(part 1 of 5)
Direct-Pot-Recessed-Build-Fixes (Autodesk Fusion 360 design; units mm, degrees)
parameter "FrameLength" = 640 comment "Fixed existing outer length"
parameter "FrameWidth" = 190 comment "Fixed existing outer width"
parameter "FrameHeight" = 110 comment "Fixed existing height"
parameter "PivotHeight" = 30 comment "Above frame center"
parameter "LeverTravel" = 100 comment "Stable endpoint to endpoint"
parameter "PrintClearance" = 0.3 comment "Prototype diametral running clearance"
base_mesh_feature "Base Mesh Feature"
ground "Pin1"
work_plane "WorkPlane1" AlongDistance -36 ExtraOffset 0
sketch "Flat load-bearing plate" plane through (-36, 0, 0) normal (1, 0, 0) x axis (0, 0, -1)
  line L1 (-33, -55) -> (-33, -75)
  line L2 (2, -55) -> (-33, -55)
  line L3 (2, 55) -> (2, -55)
  line L4 (-33, 55) -> (2, 55)
  line L5 (-33, 75) -> (-33, 55)
  line L6 (-57, 75) -> (-33, 75)
  line L7 (-57, 32) -> (-57, 75)
  line L8 (-86, 26) -> (-57, 32)
  line L9 (-86, -26) -> (-86, 26)
  line L10 (-57, -32) -> (-86, -26)
  line L11 (-57, -75) -> (-57, -32)
  line L12 (-33, -75) -> (-57, -75)
extrude "Extrude1" new body sketch "Flat load-bearing plate" along normal blind 12
work_plane "WorkPlane2" AlongDistance -37 ExtraOffset 0
sketch "Replaceable bushing seat" plane through (-37, 0, 0) normal (1, 0, 0) x axis (0, 0, -1)
  circle C1 centre (-65, 0) radius 10.15
extrude "Extrude2" cut sketch "Replaceable bushing seat" along normal blind 14
work_plane "WorkPlane3" AlongDistance -37 ExtraOffset 0
sketch "Follower pivot bolt" plane through (-37, 0, 0) normal (1, 0, 0) x axis (0, 0, -1)
  circle C1 centre (-12, -35) radius 2.7
extrude "Extrude3" cut sketch "Follower pivot bolt" along normal blind 14
work_plane "WorkPlane4" AlongDistance -76 ExtraOffset 0
sketch "M5 rail mounting bore" plane through (0, -76, 0) normal (0, 1, 0) x axis (1, 0, 0)
  circle C1 centre (-30, -45) radius 2.7
extrude "Extrude4" cut sketch "M5 rail mounting bore" along normal blind 22
work_plane "WorkPlane5" AlongDistance -55 ExtraOffset 0
sketch "Rail screw tool and washer access" plane through (0, -55, 0) normal (0, 1, 0) x axis (1, 0, 0)
  circle C1 centre (-30, -45) radius 5.3
extrude "Extrude5" cut sketch "Rail screw tool and washer access" along normal blind 12
work_plane "WorkPlane6" AlongDistance 54 ExtraOffset 0
sketch "M5 rail mounting bore (1)" plane through (0, 54, 0) normal (0, 1, 0) x axis (1, 0, 0)
  circle C1 centre (-30, -45) radius 2.7
extrude "Extrude6" cut sketch "M5 rail mounting bore (1)" along normal blind 22
work_plane "WorkPlane7" AlongDistance 43 ExtraOffset 0
sketch "Rail screw tool and washer access (1)" plane through (0, 43, 0) normal (0, 1, 0) x axis (1, 0, 0)
  circle C1 centre (-30, -45) radius 5.3
extrude "Extrude7" cut sketch "Rail screw tool and washer access (1)" along normal blind 12
work_plane "WorkPlane8" AlongDistance -37 ExtraOffset 0
sketch "Spring crossblock attachment" plane through (-37, 0, 0) normal (1, 0, 0) x axis (0, 0, -1)
  circle C1 centre (-44, -59) radius 1.7
extrude "Extrude8" cut sketch "Spring crossblock attachment" along normal blind 14
work_plane "WorkPlane9" AlongDistance -37 ExtraOffset 0
sketch "Spring crossblock attachment (1)" plane through (-37, 0, 0) normal (1, 0, 0) x axis (0, 0, -1)
  circle C1 centre (-44, -51) radius 1.7
extrude "Extrude9" cut sketch "Spring crossblock attachment (1)" along normal blind 14
work_plane "WorkPlane1" AlongDistance 24 ExtraOffset 0
sketch "Flat load-bearing plate" plane through (24, 0, 0) normal (1, 0, 0) x axis (0, 0, -1)
  line L1 (-33, -55) -> (-33, -75)
  line L2 (2, -55) -> (-33, -55)
  line L3 (2, 55) -> (2, -55)
  line L4 (-33, 55) -> (2, 55)
  line L5 (-33, 75) -> (-33, 55)
  line L6 (-57, 75) -> (-33, 75)
  line L7 (-57, 32) -> (-57, 75)
  line L8 (-86, 26) -> (-57, 32)
  line L9 (-86, -26) -> (-86, 26)
  line L10 (-57, -32) -> (-86, -26)
  line L11 (-57, -75) -> (-57, -32)
  line L12 (-33, -75) -> (-57, -75)
extrude "Extrude1" new body sketch "Flat load-bearing plate" along normal blind 12
work_plane "WorkPlane2" AlongDistance 23 ExtraOffset 0
sketch "Replaceable bushing seat" plane through (23, 0, 0) normal (1, 0, 0) x axis (0, 0, -1)
  circle C1 centre (-65, 0) radius 10.15
extrude "Extrude2" cut sketch "Replaceable bushing seat" along normal blind 14
work_plane "WorkPlane3" AlongDistance 23 ExtraOffset 0
sketch "Follower pivot bolt" plane through (23, 0, 0) normal (1, 0, 0) x axis (0, 0, -1)
  circle C1 centre (-12, -35) radius 2.7
extrude "Extrude3" cut sketch "Follower pivot bolt" along normal blind 14
work_plane "WorkPlane4" AlongDistance -76 ExtraOffset 0
sketch "M5 rail mounting bore" plane through (0, -76, 0) normal (0, 1, 0) x axis (1, 0, 0)
  circle C1 centre (30, -45) radius 2.7
extrude "Extrude4" cut sketch "M5 rail mounting bore" along normal blind 22
work_plane "WorkPlane5" AlongDistance -55 ExtraOffset 0
sketch "Rail screw tool and washer access" plane through (0, -55, 0) normal (0, 1, 0) x axis (1, 0, 0)
  circle C1 centre (30, -45) radius 5.3
extrude "Extrude5" cut sketch "Rail screw tool and washer access" along normal blind 12
work_plane "WorkPlane6" AlongDistance 54 ExtraOffset 0
sketch "M5 rail mounting bore (1)" plane through (0, 54, 0) normal (0, 1, 0) x axis (1, 0, 0)
  circle C1 centre (30, -45) radius 2.7
extrude "Extrude6" cut sketch "M5 rail mounting bore (1)" along normal blind 22
work_plane "WorkPlane7" AlongDistance 43 ExtraOffset 0
sketch "Rail screw tool and washer access (1)" plane through (0, 43, 0) normal (0, 1, 0) x axis (1, 0, 0)
  circle C1 centre (30, -45) radius 5.3
extrude "Extrude7" cut sketch "Rail screw tool and washer access (1)" along normal blind 12
work_plane "WorkPlane8" AlongDistance 23 ExtraOffset 0
sketch "Spring crossblock attachment" plane through (23, 0, 0) normal (1, 0, 0) x axis (0, 0, -1)
  circle C1 centre (-44, -59) radius 1.7
extrude "Extrude8" cut sketch "Spring crossblock attachment" along normal blind 14
work_plane "WorkPlane9" AlongDistance 23 ExtraOffset 0
sketch "Spring crossblock attachment (1)" plane through (23, 0, 0) normal (1, 0, 0) x axis (0, 0, -1)
  circle C1 centre (-44, -51) radius 1.7
extrude "Extrude9" cut sketch "Spring crossblock attachment (1)" along normal blind 14
work_plane "WorkPlane1" AlongDistance -36 ExtraOffset 0
sketch "Replaceable journal body" plane through (-36, 0, 0) normal (1, 0, 0) x axis (0, 0, -1)
  circle C1 centre (-65, 0) radius 10.05
extrude "Extrude1" new body sketch "Replaceable journal body" along normal blind 12 bodies "P03 Left flanged journal bush"
work_plane "WorkPlane2" AlongDistance -37.2 ExtraOffset 0
sketch "Axial thrust flange" plane through (-37.2, 0, 0) normal (1, 0, 0) x axis (0, 0, -1)
  circle C1 centre (-65, 0) radius 12.75
extrude "Extrude2" add sketch "Axial thrust flange" along normal blind 1.2
work_plane "WorkPlane3" AlongDistance -38 ExtraOffset 0
sketch "Running journal bore" plane through (-38, 0, 0) normal (1, 0, 0) x axis (0, 0, -1)
  circle C1 centre (-65, 0) radius 6.15
extrude "Extrude3" cut sketch "Running journal bore" along normal blind 15
work_plane "WorkPlane1" AlongDistance 24 ExtraOffset 0
sketch "Replaceable journal body" plane through (24, 0, 0) normal (1, 0, 0) x axis (0, 0, -1)
  circle C1 centre (-65, 0) radius 10.05
extrude "Extrude1" new body sketch "Replaceable journal body" along normal blind 12 bodies "P04 Right bush lower half"
work_plane "WorkPlane2" AlongDistance 36 ExtraOffset 0
sketch "Axial thrust flange" plane through (36, 0, 0) normal (1, 0, 0) x axis (0, 0, -1)
  circle C1 centre (-65, 0) radius 12.75
extrude "Extrude2" add sketch "Axial thrust flange" along normal blind 1.2
work_plane "WorkPlane3" AlongDistance 23 ExtraOffset 0
sketch "Running journal bore" plane through (23, 0, 0) normal (1, 0, 0) x axis (0, 0, -1)
  circle C1 centre (-65, 0) radius 6.15
extrude "Extrude3" cut sketch "Running journal bore" along normal blind 15
work_plane "WorkPlane1" AlongDistance -37.35 ExtraOffset 0
sketch "Continuous 12 mm journals" plane through (-37.35, 0, 0) normal (1, 0, 0) x axis (0, 0, -1)
  circle C1 centre (-65, 0) radius 6
extrude "Extrude1" new body sketch "Continuous 12 mm journals" along normal blind 74.7 bodies "P05 Shaft lower half"
work_plane "WorkPlane2" AlongDistance -23.8 ExtraOffset 0
sketch "16 mm structural shaft" plane through (-23.8, 0, 0) normal (1, 0, 0) x axis (0, 0, -1)
  circle C1 centre (-65, 0) radius 8
extrude "Extrude2" add sketch "16 mm structural shaft" along normal blind 47.6
work_plane "WorkPlane3" AlongDistance -23.9 ExtraOffset 0
sketch "D-flat torque key" plane through (-23.9, 0, 0) normal (1, 0, 0) x axis (0, 0, -1)
  line L1 (-56, 9) -> (-56, 6.5)
  line L2 (-74, 9) -> (-56, 9)
  line L3 (-74, 6.5) -> (-74, 9)
  line L4 (-56, 6.5) -> (-74, 6.5)
extrude "Extrude3" cut sketch "D-flat torque key" along normal blind 47.8
work_plane "WorkPlane4" AlongDistance 37.35 ExtraOffset 0
sketch "Integral axial shoulder" plane through (37.35, 0, 0) normal (1, 0, 0) x axis (0, 0, -1)
  circle C1 centre (-65, 0) radius 10
extrude "Extrude4" add sketch "Integral axial shoulder" along normal blind 3
work_plane "WorkPlane5" AlongDistance 40.35 ExtraOffset 0
sketch "Sensor drive stub" plane through (40.35, 0, 0) normal (1, 0, 0) x axis (0, 0, -1)
  circle C1 centre (-65, 0) radius 4
extrude "Extrude5" add sketch "Sensor drive stub" along normal blind 10
work_plane "WorkPlane6" AlongDistance 40.25 ExtraOffset 0
sketch "Sensor drive flat" plane through (40.25, 0, 0) normal (1, 0, 0) x axis (0, 0, -1)
  line L1 (-60, 5) -> (-60, 3.2)
  line L2 (-70, 5) -> (-60, 5)
  line L3 (-70, 3.2) -> (-70, 5)
  line L4 (-60, 3.2) -> (-70, 3.2)
extrude "Extrude6" cut sketch "Sensor drive flat" along normal blind 10.25
work_plane "WorkPlane7" AlongDistance -37.45 ExtraOffset 0
sketch "M3 heat-set end retention" plane through (-37.45, 0, 0) normal (1, 0, 0) x axis (0, 0, -1)
  circle C1 centre (-65, 0) radius 1.7
extrude "Extrude7" cut sketch "M3 heat-set end retention" along normal blind 6.8
work_plane "WorkPlane1" AlongDistance -39.35 ExtraOffset 0
sketch "Axial cap" plane through (-39.35, 0, 0) normal (1, 0, 0) x axis (0, 0, -1)
  circle C1 centre (-65, 0) radius 10
extrude "Extrude1" new body sketch "Axial cap" along normal blind 2 bodies "P06 Shaft retaining cap"
work_plane "WorkPlane2" AlongDistance -39.5 ExtraOffset 0
sketch "M3 cap screw" plane through (-39.5, 0, 0) normal (1, 0, 0) x axis (0, 0, -1)
  circle C1 centre (-65, 0) radius 1.7
extrude "Extrude2" cut sketch "M3 cap screw" along normal blind 2.4
work_plane "WorkPlane1" AlongDistance -7 ExtraOffset 0
sketch "Main lever hub" plane through (-7, 0, 0) normal (1, 0, 0) x axis (0, 0, -1)
  circle C1 centre (-65, 0) radius 22
extrude "Extrude1" new body sketch "Main lever hub" along normal blind 14 bodies "P07 Integral lever rotor and cam carrier"
work_plane "WorkPlane2" AlongDistance -7 ExtraOffset 0
sketch "Continuous reinforced lever stem" plane through (-7, 0, 0) normal (1, 0, 0) x axis (0, 0, -1)
  line L1 (-60, 14) -> (-60, -14)
  line L2 (-95, 11) -> (-60, 14)
  line L3 (-150, 7) -> (-95, 11)
  line L4 (-195, 7) -> (-150, 7)
  line L5 (-195, -7) -> (-195, 7)
  line L6 (-150, -7) -> (-195, -7)
  line L7 (-95, -11) -> (-150, -7)
  line L8 (-60, -14) -> (-95, -11)
extrude "Extrude2" add sketch "Continuous reinforced lever stem" along normal blind 14
work_plane "WorkPlane3" AlongDistance -7 ExtraOffset 0
sketch "Integrated cam carrier fan" plane through (-7, 0, 0) normal (1, 0, 0) x axis (0, 0, -1)
  line L1 (-44.5, 35.507) -> (-65, 0)
  line L2 (-42.6698, 34.3855) -> (-44.5, 35.507)
  line L3 (-40.9008, 33.1697) -> (-42.6698, 34.3855)
  line L4 (-39.1979, 31.863) -> (-40.9008, 33.1697)
  line L5 (-37.5656, 30.4689) -> (-39.1979, 31.863)
  line L6 (-36.0086, 28.9914) -> (-37.5656, 30.4689)
  line L7 (-34.5311, 27.4344) -> (-36.0086, 28.9914)
  line L8 (-33.137, 25.8021) -> (-34.5311, 27.4344)
  line L9 (-31.8303, 24.0992) -> (-33.137, 25.8021)
  line L10 (-30.6145, 22.3302) -> (-31.8303, 24.0992)
  line L11 (-29.493, 20.5) -> (-30.6145, 22.3302)
  line L12 (-28.4687, 18.6136) -> (-29.493, 20.5)
  line L13 (-27.5446, 16.6762) -> (-28.4687, 18.6136)
  line L14 (-26.7232, 14.6931) -> (-27.5446, 16.6762)
  line L15 (-26.0067, 12.6697) -> (-26.7232, 14.6931)
  line L16 (-25.397, 10.6116) -> (-26.0067, 12.6697)
  line L17 (-24.8959, 8.5244) -> (-25.397, 10.6116)
  line L18 (-24.5048, 6.4138) -> (-24.8959, 8.5244)
  line L19 (-24.2246, 4.2857) -> (-24.5048, 6.4138)
  line L20 (-24.0562, 2.1458) -> (-24.2246, 4.2857)
  line L21 (-24, 0) -> (-24.0562, 2.1458)
  line L22 (-24.0562, -2.1458) -> (-24, 0)
  line L23 (-24.2246, -4.2857) -> (-24.0562, -2.1458)
  line L24 (-24.5048, -6.4138) -> (-24.2246, -4.2857)
  line L25 (-24.8959, -8.5244) -> (-24.5048, -6.4138)
  line L26 (-25.397, -10.6116) -> (-24.8959, -8.5244)
  line L27 (-26.0067, -12.6697) -> (-25.397, -10.6116)
  line L28 (-26.7232, -14.6931) -> (-26.0067, -12.6697)
  line L29 (-27.5446, -16.6762) -> (-26.7232, -14.6931)
  line L30 (-28.4687, -18.6136) -> (-27.5446, -16.6762)
  line L31 (-29.493, -20.5) -> (-28.4687, -18.6136)
  line L32 (-30.6145, -22.3302) -> (-29.493, -20.5)
  line L33 (-31.8303, -24.0992) -> (-30.6145, -22.3302)
  line L34 (-33.137, -25.8021) -> (-31.8303, -24.0992)
  line L35 (-34.5311, -27.4344) -> (-33.137, -25.8021)
  line L36 (-36.0086, -28.9914) -> (-34.5311, -27.4344)
  line L37 (-37.5656, -30.4689) -> (-36.0086, -28.9914)
  line L38 (-39.1979, -31.863) -> (-37.5656, -30.4689)
  line L39 (-40.9008, -33.1697) -> (-39.1979, -31.863)
  line L40 (-42.6698, -34.3855) -> (-40.9008, -33.1697)
  line L41 (-44.5, -35.507) -> (-42.6698, -34.3855)
  line L42 (-65, 0) -> (-44.5, -35.507)
extrude "Extrude3" add sketch "Integrated cam carrier fan" along normal blind 14
work_plane "WorkPlane4" AlongDistance -23.6 ExtraOffset 0
sketch "Integral axial locating hub" plane through (-23.6, 0, 0) normal (1, 0, 0) x axis (0, 0, -1)
  circle C1 centre (-65, 0) radius 10
work_plane "WorkPlane5" AlongDistance -24 ExtraOffset 0
sketch "D shaft socket" plane through (-24, 0, 0) normal (1, 0, 0) x axis (0, 0, -1)
  line L1 (-69.6247, 6.65) -> (-60.3753, 6.65)
  arc A1 centre (-65, 0) radius 8.1 clockwise from (-60.3753, 6.65) to (-69.6247, 6.65)
extrude "Extrude5" cut sketch "D shaft socket" along normal blind 48
work_plane "WorkPlane6" AlongDistance 0.3 ExtraOffset 0
sketch "Cam M3 insert pocket" plane through (0.3, 0, 0) normal (1, 0, 0) x axis (0, 0, -1)
  circle C1 centre (-39.5442, 25.4558) radius 1.7
extrude "Extrude6" cut sketch "Cam M3 insert pocket" along normal blind 6.8
work_plane "WorkPlane7" AlongDistance 0.3 ExtraOffset 0
sketch "Cam M3 insert pocket (1)" plane through (0.3, 0, 0) normal (1, 0, 0) x axis (0, 0, -1)
  circle C1 centre (-29, 0) radius 1.7
extrude "Extrude7" cut sketch "Cam M3 insert pocket (1)" along normal blind 6.8
work_plane "WorkPlane8" AlongDistance 0.3 ExtraOffset 0
sketch "Cam M3 insert pocket (2)" plane through (0.3, 0, 0) normal (1, 0, 0) x axis (0, 0, -1)
  circle C1 centre (-39.5442, -25.4558) radius 1.7
extrude "Extrude8" cut sketch "Cam M3 insert pocket (2)" along normal blind 6.8
work_plane "WorkPlane9" AlongDistance -8 ExtraOffset 0
sketch "Grip through bolt" plane through (-8, 0, 0) normal (1, 0, 0) x axis (0, 0, -1)
  circle C1 centre (-180, 0) radius 1.7
extrude "Extrude9" cut sketch "Grip through bolt" along normal blind 16
work_plane "WorkPlane10" AlongDistance -8 ExtraOffset 0
sketch "Grip through bolt (1)" plane through (-8, 0, 0) normal (1, 0, 0) x axis (0, 0, -1)
  circle C1 centre (-190, 0) radius 1.7
extrude "Extrude10" cut sketch "Grip through bolt (1)" along normal blind 16
work_plane "WorkPlane1" AlongDistance 7 ExtraOffset 0
sketch "Roller compensated replaceable cam" plane through (7, 0, 0) normal (1, 0, 0) x axis (0, 0, -1)
  line L1 (-39.4967, 42.2602) -> (-39.6212, 42.3096)
  line L2 (-39.3834, 42.211) -> (-39.4967, 42.2602)
  line L3 (-39.2796, 42.1617) -> (-39.3834, 42.211)
  line L4 (-39.1836, 42.1119) -> (-39.2796, 42.1617)
  line L5 (-39.0932, 42.0608) -> (-39.1836, 42.1119)
  line L6 (-39.0065, 42.0075) -> (-39.0932, 42.0608)
  line L7 (-38.9215, 41.9508) -> (-39.0065, 42.0075)
  line L8 (-38.8363, 41.8895) -> (-38.9215, 41.9508)
  line L9 (-38.7492, 41.8219) -> (-38.8363, 41.8895)
  line L10 (-38.6586, 41.7465) -> (-38.7492, 41.8219)
  line L11 (-38.5633, 41.6619) -> (-38.6586, 41.7465)
  line L12 (-38.4623, 41.5665) -> (-38.5633, 41.6619)
  line L13 (-38.3549, 41.459) -> (-38.4623, 41.5665)
  line L14 (-38.2404, 41.3384) -> (-38.3549, 41.459)
  line L15 (-38.1184, 41.204) -> (-38.2404, 41.3384)
  line L16 (-37.9886, 41.055) -> (-38.1184, 41.204)
  line L17 (-37.8508, 40.8913) -> (-37.9886, 41.055)
  line L18 (-37.7045, 40.7127) -> (-37.8508, 40.8913)
  line L19 (-37.5496, 40.5196) -> (-37.7045, 40.7127)
  line L20 (-37.3856, 40.3123) -> (-37.5496, 40.5196)
  line L21 (-37.2122, 40.0915) -> (-37.3856, 40.3123)
  line L22 (-37.0289, 39.858) -> (-37.2122, 40.0915)
  line L23 (-36.8353, 39.6128) -> (-37.0289, 39.858)
  line L24 (-36.6306, 39.3571) -> (-36.8353, 39.6128)
  line L25 (-36.4145, 39.0923) -> (-36.6306, 39.3571)
  line L26 (-36.1865, 38.82) -> (-36.4145, 39.0923)
  line L27 (-35.9461, 38.5417) -> (-36.1865, 38.82)
  line L28 (-35.6932, 38.2594) -> (-35.9461, 38.5417)
  line L29 (-35.4277, 37.9751) -> (-35.6932, 38.2594)
  line L30 (-35.15, 37.6908) -> (-35.4277, 37.9751)
  line L31 (-34.8607, 37.4087) -> (-35.15, 37.6908)
  line L32 (-34.5606, 37.1307) -> (-34.8607, 37.4087)
  line L33 (-34.2512, 36.859) -> (-34.5606, 37.1307)
  line L34 (-33.934, 36.5953) -> (-34.2512, 36.859)
  line L35 (-33.6109, 36.341) -> (-33.934, 36.5953)
  line L36 (-33.2841, 36.0975) -> (-33.6109, 36.341)
  line L37 (-32.9558, 35.8655) -> (-33.2841, 36.0975)
  line L38 (-32.6282, 35.6454) -> (-32.9558, 35.8655)
  line L39 (-32.3036, 35.4375) -> (-32.6282, 35.6454)
  line L40 (-31.984, 35.2415) -> (-32.3036, 35.4375)
  line L41 (-31.6712, 35.057) -> (-31.984, 35.2415)
  line L42 (-31.3671, 34.8833) -> (-31.6712, 35.057)
  line L43 (-31.073, 34.7197) -> (-31.3671, 34.8833)
  line L44 (-30.7902, 34.5655) -> (-31.073, 34.7197)
  line L45 (-30.52, 34.4197) -> (-30.7902, 34.5655)
  line L46 (-30.263, 34.2816) -> (-30.52, 34.4197)
  line L47 (-30.0201, 34.1506) -> (-30.263, 34.2816)
  line L48 (-29.7919, 34.0259) -> (-30.0201, 34.1506)
  line L49 (-29.5787, 33.9071) -> (-29.7919, 34.0259)
  line L50 (-29.3807, 33.7939) -> (-29.5787, 33.9071)
  line L51 (-29.1982, 33.6858) -> (-29.3807, 33.7939)
  line L52 (-29.0309, 33.5827) -> (-29.1982, 33.6858)
  line L53 (-28.8786, 33.4843) -> (-29.0309, 33.5827)
  line L54 (-28.7406, 33.3906) -> (-28.8786, 33.4843)
  line L55 (-28.6164, 33.3013) -> (-28.7406, 33.3906)
  line L56 (-28.5047, 33.2161) -> (-28.6164, 33.3013)
  line L57 (-28.4046, 33.1346) -> (-28.5047, 33.2161)
  line L58 (-28.3144, 33.0563) -> (-28.4046, 33.1346)
  line L59 (-28.2327, 32.9802) -> (-28.3144, 33.0563)
  line L60 (-28.1577, 32.9052) -> (-28.2327, 32.9802)
  line L61 (-28.0879, 32.8301) -> (-28.1577, 32.9052)
  line L62 (-28.0214, 32.7532) -> (-28.0879, 32.8301)
  line L63 (-27.9569, 32.6728) -> (-28.0214, 32.7532)
  line L64 (-27.893, 32.5869) -> (-27.9569, 32.6728)
  line L65 (-27.8285, 32.4936) -> (-27.893, 32.5869)
  line L66 (-27.7627, 32.3911) -> (-27.8285, 32.4936)
  line L67 (-27.6947, 32.2776) -> (-27.7627, 32.3911)
  line L68 (-27.6241, 32.1514) -> (-27.6947, 32.2776)
  line L69 (-27.5507, 32.0113) -> (-27.6241, 32.1514)
  line L70 (-27.4742, 31.8562) -> (-27.5507, 32.0113)
  line L71 (-27.3945, 31.6853) -> (-27.4742, 31.8562)
  line L72 (-27.3113, 31.4981) -> (-27.3945, 31.6853)
  line L73 (-27.2245, 31.2943) -> (-27.3113, 31.4981)
  line L74 (-27.1338, 31.074) -> (-27.2245, 31.2943)
  line L75 (-27.0388, 30.8373) -> (-27.1338, 31.074)
  line L76 (-26.939, 30.5847) -> (-27.0388, 30.8373)
  line L77 (-26.8337, 30.3166) -> (-26.939, 30.5847)
  line L78 (-26.7223, 30.034) -> (-26.8337, 30.3166)
  line L79 (-26.6038, 29.7375) -> (-26.7223, 30.034)
  line L80 (-26.4775, 29.4284) -> (-26.6038, 29.7375)
  line L81 (-26.3424, 29.1079) -> (-26.4775, 29.4284)
  line L82 (-26.1977, 28.7772) -> (-26.3424, 29.1079)
  line L83 (-26.0425, 28.4382) -> (-26.1977, 28.7772)
  line L84 (-25.8761, 28.0925) -> (-26.0425, 28.4382)
  line L85 (-25.6981, 27.7422) -> (-25.8761, 28.0925)
  line L86 (-25.5084, 27.3893) -> (-25.6981, 27.7422)
  line L87 (-25.3069, 27.0362) -> (-25.5084, 27.3893)
  line L88 (-25.0943, 26.6851) -> (-25.3069, 27.0362)
  line L89 (-24.8713, 26.3382) -> (-25.0943, 26.6851)
  line L90 (-24.6392, 25.9976) -> (-24.8713, 26.3382)
  line L91 (-24.3995, 25.6653) -> (-24.6392, 25.9976)
  line L92 (-24.1539, 25.3428) -> (-24.3995, 25.6653)
  line L93 (-23.9045, 25.0314) -> (-24.1539, 25.3428)
  line L94 (-23.6532, 24.7321) -> (-23.9045, 25.0314)
  line L95 (-23.4022, 24.4455) -> (-23.6532, 24.7321)
  line L96 (-23.1534, 24.1718) -> (-23.4022, 24.4455)
  line L97 (-22.9088, 23.9111) -> (-23.1534, 24.1718)
  line L98 (-22.6701, 23.6631) -> (-22.9088, 23.9111)
  line L99 (-22.4387, 23.4276) -> (-22.6701, 23.6631)
  line L100 (-22.2162, 23.204) -> (-22.4387, 23.4276)
  line L101 (-22.0036, 22.9918) -> (-22.2162, 23.204)
  line L102 (-21.8021, 22.7907) -> (-22.0036, 22.9918)
  line L103 (-21.6123, 22.6001) -> (-21.8021, 22.7907)
  line L104 (-21.435, 22.4197) -> (-21.6123, 22.6001)
  line L105 (-21.2706, 22.2491) -> (-21.435, 22.4197)
  line L106 (-21.1193, 22.088) -> (-21.2706, 22.2491)
  line L107 (-20.9813, 21.9362) -> (-21.1193, 22.088)
  line L108 (-20.8565, 21.7934) -> (-20.9813, 21.9362)
  line L109 (-20.7443, 21.6594) -> (-20.8565, 21.7934)
  line L110 (-20.6444, 21.5337) -> (-20.7443, 21.6594)
  line L111 (-20.556, 21.4159) -> (-20.6444, 21.5337)
  line L112 (-20.478, 21.3055) -> (-20.556, 21.4159)
  line L113 (-20.4094, 21.2014) -> (-20.478, 21.3055)
  line L114 (-20.349, 21.1027) -> (-20.4094, 21.2014)
  line L115 (-20.2954, 21.0079) -> (-20.349, 21.1027)
  line L116 (-20.2475, 20.9154) -> (-20.2954, 21.0079)
  line L117 (-20.2039, 20.8234) -> (-20.2475, 20.9154)
  line L118 (-20.1637, 20.7297) -> (-20.2039, 20.8234)
  line L119 (-20.126, 20.6321) -> (-20.1637, 20.7297)
  line L120 (-20.0901, 20.5286) -> (-20.126, 20.6321)
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extrude "Extrude1" new body sketch "Roller compensated replaceable cam" along normal blind 8 bodies "P08 Cam 7 gates - stable endpoints"
work_plane "WorkPlane2" AlongDistance 6.9 ExtraOffset 0
sketch "Cam screw clearance" plane through (6.9, 0, 0) normal (1, 0, 0) x axis (0, 0, -1)
  circle C1 centre (-39.5442, 25.4558) radius 1.7
extrude "Extrude2" cut sketch "Cam screw clearance" along normal blind 8.2
work_plane "WorkPlane3" AlongDistance 12 ExtraOffset 0
sketch "Cam head recess" plane through (12, 0, 0) normal (1, 0, 0) x axis (0, 0, -1)
  circle C1 centre (-39.5442, 25.4558) radius 3.1
extrude "Extrude3" cut sketch "Cam head recess" along normal blind 3.1
work_plane "WorkPlane4" AlongDistance 6.9 ExtraOffset 0
sketch "Cam screw clearance (1)" plane through (6.9, 0, 0) normal (1, 0, 0) x axis (0, 0, -1)
  circle C1 centre (-29, 0) radius 1.7
extrude "Extrude4" cut sketch "Cam screw clearance (1)" along normal blind 8.2
work_plane "WorkPlane5" AlongDistance 12 ExtraOffset 0
sketch "Cam head recess (1)" plane through (12, 0, 0) normal (1, 0, 0) x axis (0, 0, -1)
  circle C1 centre (-29, 0) radius 3.1
extrude "Extrude5" cut sketch "Cam head recess (1)" along normal blind 3.1
work_plane "WorkPlane6" AlongDistance 6.9 ExtraOffset 0
sketch "Cam screw clearance (2)" plane through (6.9, 0, 0) normal (1, 0, 0) x axis (0, 0, -1)
  circle C1 centre (-39.5442, -25.4558) radius 1.7
extrude "Extrude6" cut sketch "Cam screw clearance (2)" along normal blind 8.2
work_plane "WorkPlane7" AlongDistance 12 ExtraOffset 0
sketch "Cam head recess (2)" plane through (12, 0, 0) normal (1, 0, 0) x axis (0, 0, -1)
  circle C1 centre (-39.5442, -25.4558) radius 3.1
extrude "Extrude7" cut sketch "Cam head recess (2)" along normal blind 3.1
work_plane "WorkPlane1" AlongDistance 7 ExtraOffset 0
sketch "Roller compensated replaceable cam" plane through (7, 0, 0) normal (1, 0, 0) x axis (0, 0, -1)
  line L1 (-40.6423, 42.8316) -> (-40.8055, 42.9534)
  line L2 (-40.4783, 42.705) -> (-40.6423, 42.8316)
  line L3 (-40.3132, 42.5736) -> (-40.4783, 42.705)
  line L4 (-40.1469, 42.4372) -> (-40.3132, 42.5736)
  line L5 (-39.9791, 42.2958) -> (-40.1469, 42.4372)
  line L6 (-39.8097, 42.1493) -> (-39.9791, 42.2958)
  line L7 (-39.6386, 41.9977) -> (-39.8097, 42.1493)
  line L8 (-39.4656, 41.8411) -> (-39.6386, 41.9977)
  line L9 (-39.2906, 41.6794) -> (-39.4656, 41.8411)
  line L10 (-39.1134, 41.5128) -> (-39.2906, 41.6794)
  line L11 (-38.9338, 41.3413) -> (-39.1134, 41.5128)
  line L12 (-38.7519, 41.165) -> (-38.9338, 41.3413)
  line L13 (-38.5674, 40.9842) -> (-38.7519, 41.165)
  line L14 (-38.3803, 40.7991) -> (-38.5674, 40.9842)
  line L15 (-38.1904, 40.6097) -> (-38.3803, 40.7991)
  line L16 (-37.9976, 40.4164) -> (-38.1904, 40.6097)
  line L17 (-37.8019, 40.2195) -> (-37.9976, 40.4164)
  line L18 (-37.6031, 40.0191) -> (-37.8019, 40.2195)
  line L19 (-37.4011, 39.8157) -> (-37.6031, 40.0191)
  line L20 (-37.1958, 39.6094) -> (-37.4011, 39.8157)
  line L21 (-36.9872, 39.4008) -> (-37.1958, 39.6094)
  line L22 (-36.7753, 39.19) -> (-36.9872, 39.4008)
  line L23 (-36.5599, 38.9775) -> (-36.7753, 39.19)
  line L24 (-36.3411, 38.7636) -> (-36.5599, 38.9775)
  line L25 (-36.1189, 38.5488) -> (-36.3411, 38.7636)
  line L26 (-35.8933, 38.3333) -> (-36.1189, 38.5488)
  line L27 (-35.6644, 38.1177) -> (-35.8933, 38.3333)
  line L28 (-35.4322, 37.9021) -> (-35.6644, 38.1177)
  line L29 (-35.197, 37.6871) -> (-35.4322, 37.9021)
  line L30 (-34.9588, 37.473) -> (-35.197, 37.6871)
  line L31 (-34.7178, 37.2602) -> (-34.9588, 37.473)
  line L32 (-34.4743, 37.0489) -> (-34.7178, 37.2602)
  line L33 (-34.2286, 36.8395) -> (-34.4743, 37.0489)
  line L34 (-33.9808, 36.6322) -> (-34.2286, 36.8395)
  line L35 (-33.7314, 36.4274) -> (-33.9808, 36.6322)
  line L36 (-33.4806, 36.2252) -> (-33.7314, 36.4274)
  line L37 (-33.2289, 36.0258) -> (-33.4806, 36.2252)
  line L38 (-32.9765, 35.8294) -> (-33.2289, 36.0258)
  line L39 (-32.7239, 35.6361) -> (-32.9765, 35.8294)
  line L40 (-32.4714, 35.446) -> (-32.7239, 35.6361)
  line L41 (-32.2195, 35.259) -> (-32.4714, 35.446)
  line L42 (-31.9685, 35.0753) -> (-32.2195, 35.259)
  line L43 (-31.7188, 34.8948) -> (-31.9685, 35.0753)
  line L44 (-31.4708, 34.7175) -> (-31.7188, 34.8948)
  line L45 (-31.2249, 34.5432) -> (-31.4708, 34.7175)
  line L46 (-30.9813, 34.3719) -> (-31.2249, 34.5432)
  line L47 (-30.7405, 34.2034) -> (-30.9813, 34.3719)
  line L48 (-30.5027, 34.0377) -> (-30.7405, 34.2034)
  line L49 (-30.2682, 33.8746) -> (-30.5027, 34.0377)
  line L50 (-30.0373, 33.7139) -> (-30.2682, 33.8746)
  line L51 (-29.8103, 33.5555) -> (-30.0373, 33.7139)
  line L52 (-29.5875, 33.3992) -> (-29.8103, 33.5555)
  line L53 (-29.3689, 33.2448) -> (-29.5875, 33.3992)
  line L54 (-29.1548, 33.0923) -> (-29.3689, 33.2448)
  line L55 (-28.9455, 32.9414) -> (-29.1548, 33.0923)
  line L56 (-28.7409, 32.7921) -> (-28.9455, 32.9414)
  line L57 (-28.5413, 32.644) -> (-28.7409, 32.7921)
  line L58 (-28.3468, 32.4972) -> (-28.5413, 32.644)
  line L59 (-28.1574, 32.3515) -> (-28.3468, 32.4972)
  line L60 (-27.9732, 32.2068) -> (-28.1574, 32.3515)
  line L61 (-27.7942, 32.0628) -> (-27.9732, 32.2068)
  line L62 (-27.6204, 31.9196) -> (-27.7942, 32.0628)
  line L63 (-27.4518, 31.7769) -> (-27.6204, 31.9196)
  line L64 (-27.2884, 31.6347) -> (-27.4518, 31.7769)
  line L65 (-27.1301, 31.4927) -> (-27.2884, 31.6347)
  line L66 (-26.9767, 31.351) -> (-27.1301, 31.4927)
  line L67 (-26.8282, 31.2092) -> (-26.9767, 31.351)
  line L68 (-26.6843, 31.0673) -> (-26.8282, 31.2092)
  line L69 (-26.545, 30.925) -> (-26.6843, 31.0673)
  line L70 (-26.4101, 30.7822) -> (-26.545, 30.925)
  line L71 (-26.2793, 30.6387) -> (-26.4101, 30.7822)
  line L72 (-26.1524, 30.4942) -> (-26.2793, 30.6387)
  line L73 (-26.0293, 30.3485) -> (-26.1524, 30.4942)
  line L74 (-25.9096, 30.2013) -> (-26.0293, 30.3485)
  line L75 (-25.7932, 30.0524) -> (-25.9096, 30.2013)
  line L76 (-25.6797, 29.9015) -> (-25.7932, 30.0524)
  line L77 (-25.5691, 29.7482) -> (-25.6797, 29.9015)
  line L78 (-25.461, 29.5923) -> (-25.5691, 29.7482)
  line L79 (-25.3553, 29.4334) -> (-25.461, 29.5923)
  line L80 (-25.2517, 29.2713) -> (-25.3553, 29.4334)
  line L81 (-25.15, 29.1057) -> (-25.2517, 29.2713)
  line L82 (-25.0502, 28.9363) -> (-25.15, 29.1057)
  line L83 (-24.9519, 28.7628) -> (-25.0502, 28.9363)
  line L84 (-24.855, 28.5849) -> (-24.9519, 28.7628)
  line L85 (-24.7595, 28.4024) -> (-24.855, 28.5849)
  line L86 (-24.665, 28.2152) -> (-24.7595, 28.4024)
  line L87 (-24.5716, 28.023) -> (-24.665, 28.2152)
  line L88 (-24.4791, 27.8257) -> (-24.5716, 28.023)
  line L89 (-24.3873, 27.6231) -> (-24.4791, 27.8257)
  line L90 (-24.2961, 27.4152) -> (-24.3873, 27.6231)
  line L91 (-24.2054, 27.2019) -> (-24.2961, 27.4152)
  line L92 (-24.115, 26.9832) -> (-24.2054, 27.2019)
  line L93 (-24.0247, 26.7591) -> (-24.115, 26.9832)
  line L94 (-23.9346, 26.5296) -> (-24.0247, 26.7591)
  line L95 (-23.8442, 26.2947) -> (-23.9346, 26.5296)
  line L96 (-23.7536, 26.0546) -> (-23.8442, 26.2947)
  line L97 (-23.6625, 25.8094) -> (-23.7536, 26.0546)
  line L98 (-23.5707, 25.5592) -> (-23.6625, 25.8094)
  line L99 (-23.478, 25.3041) -> (-23.5707, 25.5592)
  line L100 (-23.3842, 25.0444) -> (-23.478, 25.3041)
  line L101 (-23.2891, 24.7802) -> (-23.3842, 25.0444)
  line L102 (-23.1926, 24.5118) -> (-23.2891, 24.7802)
  line L103 (-23.0943, 24.2394) -> (-23.1926, 24.5118)
  line L104 (-22.9942, 23.9633) -> (-23.0943, 24.2394)
  line L105 (-22.8919, 23.6838) -> (-22.9942, 23.9633)
  line L106 (-22.7873, 23.4012) -> (-22.8919, 23.6838)
  line L107 (-22.6803, 23.1157) -> (-22.7873, 23.4012)
  line L108 (-22.5706, 22.8278) -> (-22.6803, 23.1157)
  line L109 (-22.4581, 22.5379) -> (-22.5706, 22.8278)
  line L110 (-22.3428, 22.2461) -> (-22.4581, 22.5379)
  line L111 (-22.2245, 21.953) -> (-22.3428, 22.2461)
  line L112 (-22.1031, 21.659) -> (-22.2245, 21.953)
  line L113 (-21.9788, 21.3644) -> (-22.1031, 21.659)
  line L114 (-21.8513, 21.0696) -> (-21.9788, 21.3644)
  line L115 (-21.7209, 20.7751) -> (-21.8513, 21.0696)
  line L116 (-21.5876, 20.4811) -> (-21.7209, 20.7751)
  line L117 (-21.4516, 20.1882) -> (-21.5876, 20.4811)
  line L118 (-21.3129, 19.8966) -> (-21.4516, 20.1882)
  line L119 (-21.1718, 19.6067) -> (-21.3129, 19.8966)
  line L120 (-21.0286, 19.3189) -> (-21.1718, 19.6067)
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extrude "Extrude1" new body sketch "Roller compensated replaceable cam" along normal blind 8 bodies "P08 Cam 5 gates - stable endpoints"
work_plane "WorkPlane2" AlongDistance 6.9 ExtraOffset 0
sketch "Cam screw clearance" plane through (6.9, 0, 0) normal (1, 0, 0) x axis (0, 0, -1)
  circle C1 centre (-39.5442, 25.4558) radius 1.7
extrude "Extrude2" cut sketch "Cam screw clearance" along normal blind 8.2
work_plane "WorkPlane3" AlongDistance 12 ExtraOffset 0
sketch "Cam head recess" plane through (12, 0, 0) normal (1, 0, 0) x axis (0, 0, -1)
  circle C1 centre (-39.5442, 25.4558) radius 3.1
extrude "Extrude3" cut sketch "Cam head recess" along normal blind 3.1
work_plane "WorkPlane4" AlongDistance 6.9 ExtraOffset 0
sketch "Cam screw clearance (1)" plane through (6.9, 0, 0) normal (1, 0, 0) x axis (0, 0, -1)
  circle C1 centre (-29, 0) radius 1.7
extrude "Extrude4" cut sketch "Cam screw clearance (1)" along normal blind 8.2
work_plane "WorkPlane5" AlongDistance 12 ExtraOffset 0
sketch "Cam head recess (1)" plane through (12, 0, 0) normal (1, 0, 0) x axis (0, 0, -1)
  circle C1 centre (-29, 0) radius 3.1
extrude "Extrude5" cut sketch "Cam head recess (1)" along normal blind 3.1
work_plane "WorkPlane6" AlongDistance 6.9 ExtraOffset 0
sketch "Cam screw clearance (2)" plane through (6.9, 0, 0) normal (1, 0, 0) x axis (0, 0, -1)
  circle C1 centre (-39.5442, -25.4558) radius 1.7
extrude "Extrude6" cut sketch "Cam screw clearance (2)" along normal blind 8.2
work_plane "WorkPlane7" AlongDistance 12 ExtraOffset 0
sketch "Cam head recess (2)" plane through (12, 0, 0) normal (1, 0, 0) x axis (0, 0, -1)
  circle C1 centre (-39.5442, -25.4558) radius 3.1
extrude "Extrude7" cut sketch "Cam head recess (2)" along normal blind 3.1
work_plane "WorkPlane1" AlongDistance 7 ExtraOffset 0
sketch "Roller compensated replaceable cam" plane through (7, 0, 0) normal (1, 0, 0) x axis (0, 0, -1)
  line L1 (-40.92, 42.0772) -> (-41.1325, 42.2273)
  line L2 (-40.7077, 41.9259) -> (-40.92, 42.0772)
  line L3 (-40.4956, 41.7734) -> (-40.7077, 41.9259)
  line L4 (-40.2838, 41.6199) -> (-40.4956, 41.7734)
  line L5 (-40.0721, 41.4654) -> (-40.2838, 41.6199)
  line L6 (-39.8606, 41.3098) -> (-40.0721, 41.4654)
  line L7 (-39.6492, 41.1532) -> (-39.8606, 41.3098)
  line L8 (-39.4381, 40.9957) -> (-39.6492, 41.1532)
  line L9 (-39.2271, 40.8372) -> (-39.4381, 40.9957)
  line L10 (-39.0163, 40.6779) -> (-39.2271, 40.8372)
  line L11 (-38.8057, 40.5176) -> (-39.0163, 40.6779)
  line L12 (-38.5952, 40.3566) -> (-38.8057, 40.5176)
  line L13 (-38.3849, 40.1947) -> (-38.5952, 40.3566)
  line L14 (-38.1747, 40.032) -> (-38.3849, 40.1947)
  line L15 (-37.9647, 39.8686) -> (-38.1747, 40.032)
  line L16 (-37.7549, 39.7045) -> (-37.9647, 39.8686)
  line L17 (-37.5452, 39.5397) -> (-37.7549, 39.7045)
  line L18 (-37.3357, 39.3742) -> (-37.5452, 39.5397)
  line L19 (-37.1263, 39.2081) -> (-37.3357, 39.3742)
  line L20 (-36.9171, 39.0413) -> (-37.1263, 39.2081)
  line L21 (-36.7081, 38.874) -> (-36.9171, 39.0413)
  line L22 (-36.4992, 38.7061) -> (-36.7081, 38.874)
  line L23 (-36.2905, 38.5376) -> (-36.4992, 38.7061)
  line L24 (-36.082, 38.3687) -> (-36.2905, 38.5376)
  line L25 (-35.8737, 38.1992) -> (-36.082, 38.3687)
  line L26 (-35.6656, 38.0292) -> (-35.8737, 38.1992)
  line L27 (-35.4577, 37.8588) -> (-35.6656, 38.0292)
  line L28 (-35.25, 37.688) -> (-35.4577, 37.8588)
  line L29 (-35.0425, 37.5167) -> (-35.25, 37.688)
  line L30 (-34.8352, 37.3451) -> (-35.0425, 37.5167)
  line L31 (-34.6282, 37.173) -> (-34.8352, 37.3451)
  line L32 (-34.4215, 37.0006) -> (-34.6282, 37.173)
  line L33 (-34.215, 36.8278) -> (-34.4215, 37.0006)
  line L34 (-34.0088, 36.6547) -> (-34.215, 36.8278)
  line L35 (-33.8028, 36.4812) -> (-34.0088, 36.6547)
  line L36 (-33.5972, 36.3074) -> (-33.8028, 36.4812)
  line L37 (-33.392, 36.1333) -> (-33.5972, 36.3074)
  line L38 (-33.187, 35.9589) -> (-33.392, 36.1333)
  line L39 (-32.9825, 35.7842) -> (-33.187, 35.9589)
  line L40 (-32.7783, 35.6093) -> (-32.9825, 35.7842)
  line L41 (-32.5745, 35.434) -> (-32.7783, 35.6093)
  line L42 (-32.3711, 35.2584) -> (-32.5745, 35.434)
  line L43 (-32.1682, 35.0826) -> (-32.3711, 35.2584)
  line L44 (-31.9657, 34.9065) -> (-32.1682, 35.0826)
  line L45 (-31.7637, 34.7302) -> (-31.9657, 34.9065)
  line L46 (-31.5623, 34.5535) -> (-31.7637, 34.7302)
  line L47 (-31.3613, 34.3766) -> (-31.5623, 34.5535)
  line L48 (-31.1609, 34.1994) -> (-31.3613, 34.3766)
  line L49 (-30.9611, 34.0219) -> (-31.1609, 34.1994)
  line L50 (-30.7619, 33.8442) -> (-30.9611, 34.0219)
  line L51 (-30.5634, 33.6662) -> (-30.7619, 33.8442)
  line L52 (-30.3654, 33.4878) -> (-30.5634, 33.6662)
  line L53 (-30.1682, 33.3092) -> (-30.3654, 33.4878)
  line L54 (-29.9717, 33.1303) -> (-30.1682, 33.3092)
  line L55 (-29.7759, 32.9511) -> (-29.9717, 33.1303)
  line L56 (-29.5809, 32.7715) -> (-29.7759, 32.9511)
  line L57 (-29.3866, 32.5916) -> (-29.5809, 32.7715)
  line L58 (-29.1932, 32.4114) -> (-29.3866, 32.5916)
  line L59 (-29.0007, 32.2308) -> (-29.1932, 32.4114)
  line L60 (-28.809, 32.0499) -> (-29.0007, 32.2308)
  line L61 (-28.6182, 31.8686) -> (-28.809, 32.0499)
  line L62 (-28.4284, 31.6869) -> (-28.6182, 31.8686)
  line L63 (-28.2395, 31.5048) -> (-28.4284, 31.6869)
  line L64 (-28.0516, 31.3224) -> (-28.2395, 31.5048)
  line L65 (-27.8647, 31.1395) -> (-28.0516, 31.3224)
  line L66 (-27.6789, 30.9562) -> (-27.8647, 31.1395)
  line L67 (-27.4942, 30.7724) -> (-27.6789, 30.9562)
  line L68 (-27.3106, 30.5882) -> (-27.4942, 30.7724)
  line L69 (-27.1281, 30.4035) -> (-27.3106, 30.5882)
  line L70 (-26.9468, 30.2184) -> (-27.1281, 30.4035)
  line L71 (-26.7667, 30.0327) -> (-26.9468, 30.2184)
  line L72 (-26.5878, 29.8465) -> (-26.7667, 30.0327)
  line L73 (-26.4102, 29.6599) -> (-26.5878, 29.8465)
  line L74 (-26.2338, 29.4727) -> (-26.4102, 29.6599)
  line L75 (-26.0588, 29.2849) -> (-26.2338, 29.4727)
  line L76 (-25.8851, 29.0966) -> (-26.0588, 29.2849)
  line L77 (-25.7127, 28.9078) -> (-25.8851, 29.0966)
  line L78 (-25.5418, 28.7183) -> (-25.7127, 28.9078)
  line L79 (-25.3723, 28.5283) -> (-25.5418, 28.7183)
  line L80 (-25.2042, 28.3376) -> (-25.3723, 28.5283)
  line L81 (-25.0376, 28.1464) -> (-25.2042, 28.3376)
  line L82 (-24.8725, 27.9545) -> (-25.0376, 28.1464)
  line L83 (-24.7089, 27.762) -> (-24.8725, 27.9545)
  line L84 (-24.5469, 27.5688) -> (-24.7089, 27.762)
  line L85 (-24.3864, 27.375) -> (-24.5469, 27.5688)
  line L86 (-24.2275, 27.1805) -> (-24.3864, 27.375)
  line L87 (-24.0703, 26.9854) -> (-24.2275, 27.1805)
  line L88 (-23.9146, 26.7895) -> (-24.0703, 26.9854)
  line L89 (-23.7607, 26.593) -> (-23.9146, 26.7895)
  line L90 (-23.6084, 26.3958) -> (-23.7607, 26.593)
  line L91 (-23.4578, 26.1978) -> (-23.6084, 26.3958)
  line L92 (-23.3089, 25.9992) -> (-23.4578, 26.1978)
  line L93 (-23.1618, 25.7998) -> (-23.3089, 25.9992)
  line L94 (-23.0164, 25.5997) -> (-23.1618, 25.7998)
  line L95 (-22.8728, 25.3988) -> (-23.0164, 25.5997)
  line L96 (-22.7309, 25.1972) -> (-22.8728, 25.3988)
  line L97 (-22.5909, 24.9949) -> (-22.7309, 25.1972)
  line L98 (-22.4527, 24.7917) -> (-22.5909, 24.9949)
  line L99 (-22.3163, 24.5879) -> (-22.4527, 24.7917)
  line L100 (-22.1817, 24.3832) -> (-22.3163, 24.5879)
  line L101 (-22.049, 24.1778) -> (-22.1817, 24.3832)
  line L102 (-21.9182, 23.9716) -> (-22.049, 24.1778)
  line L103 (-21.7892, 23.7646) -> (-21.9182, 23.9716)
  line L104 (-21.6622, 23.5568) -> (-21.7892, 23.7646)
  line L105 (-21.537, 23.3482) -> (-21.6622, 23.5568)
  line L106 (-21.4137, 23.1388) -> (-21.537, 23.3482)
  line L107 (-21.2923, 22.9286) -> (-21.4137, 23.1388)
  line L108 (-21.1728, 22.7176) -> (-21.2923, 22.9286)
  line L109 (-21.0553, 22.5058) -> (-21.1728, 22.7176)
  line L110 (-20.9397, 22.2931) -> (-21.0553, 22.5058)
  line L111 (-20.8259, 22.0796) -> (-20.9397, 22.2931)
  line L112 (-20.7142, 21.8653) -> (-20.8259, 22.0796)
  line L113 (-20.6043, 21.6502) -> (-20.7142, 21.8653)
  line L114 (-20.4964, 21.4342) -> (-20.6043, 21.6502)
  line L115 (-20.3904, 21.2174) -> (-20.4964, 21.4342)
  line L116 (-20.2863, 20.9997) -> (-20.3904, 21.2174)
  line L117 (-20.1842, 20.7812) -> (-20.2863, 20.9997)
  line L118 (-20.0839, 20.5618) -> (-20.1842, 20.7812)
  line L119 (-19.9856, 20.3416) -> (-20.0839, 20.5618)
  line L120 (-19.8892, 20.1205) -> (-19.9856, 20.3416)
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extrude "Extrude1" new body sketch "Roller compensated replaceable cam" along normal blind 8 bodies "P08 Cam 3 gates - stable endpoints"
work_plane "WorkPlane2" AlongDistance 6.9 ExtraOffset 0
sketch "Cam screw clearance" plane through (6.9, 0, 0) normal (1, 0, 0) x axis (0, 0, -1)
  circle C1 centre (-39.5442, 25.4558) radius 1.7
extrude "Extrude2" cut sketch "Cam screw clearance" along normal blind 8.2
work_plane "WorkPlane3" AlongDistance 12 ExtraOffset 0
sketch "Cam head recess" plane through (12, 0, 0) normal (1, 0, 0) x axis (0, 0, -1)
  circle C1 centre (-39.5442, 25.4558) radius 3.1
extrude "Extrude3" cut sketch "Cam head recess" along normal blind 3.1
work_plane "WorkPlane4" AlongDistance 6.9 ExtraOffset 0
sketch "Cam screw clearance (1)" plane through (6.9, 0, 0) normal (1, 0, 0) x axis (0, 0, -1)
  circle C1 centre (-29, 0) radius 1.7
extrude "Extrude4" cut sketch "Cam screw clearance (1)" along normal blind 8.2
work_plane "WorkPlane5" AlongDistance 12 ExtraOffset 0
sketch "Cam head recess (1)" plane through (12, 0, 0) normal (1, 0, 0) x axis (0, 0, -1)
  circle C1 centre (-29, 0) radius 3.1
extrude "Extrude5" cut sketch "Cam head recess (1)" along normal blind 3.1
work_plane "WorkPlane6" AlongDistance 6.9 ExtraOffset 0
sketch "Cam screw clearance (2)" plane through (6.9, 0, 0) normal (1, 0, 0) x axis (0, 0, -1)
  circle C1 centre (-39.5442, -25.4558) radius 1.7
extrude "Extrude6" cut sketch "Cam screw clearance (2)" along normal blind 8.2
work_plane "WorkPlane7" AlongDistance 12 ExtraOffset 0
sketch "Cam head recess (2)" plane through (12, 0, 0) normal (1, 0, 0) x axis (0, 0, -1)
  circle C1 centre (-39.5442, -25.4558) radius 3.1
extrude "Extrude7" cut sketch "Cam head recess (2)" along normal blind 3.1
work_plane "WorkPlane1" AlongDistance 0 ExtraOffset 0
sketch "Palm grip smooth contour" plane through (0, 0, 0) normal (1, 0, 0) x axis (0, 0, -1)
  curve K1 (-225, 0) -> (-165, 12)
  line L1 (-225, 0) -> (-165, 0)
  line L2 (-165, 12) -> (-165, 0)
revolve "Revolve1" sketch "Palm grip smooth contour" AlongAngle 360 bodies "P09 Grip insert half"
work_plane "WorkPlane2" AlongDistance 0 ExtraOffset 0
sketch "Split on print bed face" plane through (0, 0, 0) normal (1, 0, 0) x axis (0, 0, -1)
  line L1 (-160, 30) -> (-160, -30)
  line L2 (-230, 30) -> (-160, 30)
  line L3 (-230, -30) -> (-230, 30)
  line L4 (-160, -30) -> (-230, -30)
extrude "Extrude1" cut sketch "Split on print bed face" along normal blind 30
work_plane "WorkPlane3" AlongDistance -7.2 ExtraOffset 0
sketch "Keyed stem socket" plane through (-7.2, 0, 0) normal (1, 0, 0) x axis (0, 0, -1)
  line L1 (-164, 7.2) -> (-164, -7.2)
  line L2 (-196, 7.2) -> (-164, 7.2)
  line L3 (-196, -7.2) -> (-196, 7.2)
  line L4 (-164, -7.2) -> (-196, -7.2)
extrude "Extrude2" cut sketch "Keyed stem socket" along normal blind 14.4
work_plane "WorkPlane4" AlongDistance -13.9 ExtraOffset 0
sketch "M3 grip heat set" plane through (-13.9, 0, 0) normal (1, 0, 0) x axis (0, 0, -1)
  circle C1 centre (-180, 0) radius 1.9
extrude "Extrude3" cut sketch "M3 grip heat set" along normal blind 6.8
work_plane "WorkPlane5" AlongDistance -13.9 ExtraOffset 0
sketch "M3 grip heat set (1)" plane through (-13.9, 0, 0) normal (1, 0, 0) x axis (0, 0, -1)
  circle C1 centre (-190, 0) radius 1.9
extrude "Extrude4" cut sketch "M3 grip heat set (1)" along normal blind 6.8
work_plane "WorkPlane1" AlongDistance 0 ExtraOffset 0
sketch "Palm grip smooth contour" plane through (0, 0, 0) normal (1, 0, 0) x axis (0, 0, -1)
  curve K1 (-225, 0) -> (-165, 12)
  line L1 (-225, 0) -> (-165, 0)
  line L2 (-165, 12) -> (-165, 0)
revolve "Revolve1" sketch "Palm grip smooth contour" AlongAngle 360 bodies "P10 Grip screw half"
work_plane "WorkPlane2" AlongDistance -30 ExtraOffset 0
sketch "Split on print bed face" plane through (-30, 0, 0) normal (1, 0, 0) x axis (0, 0, -1)
  line L1 (-160, 30) -> (-160, -30)
  line L2 (-230, 30) -> (-160, 30)
  line L3 (-230, -30) -> (-230, 30)
  line L4 (-160, -30) -> (-230, -30)
extrude "Extrude1" cut sketch "Split on print bed face" along normal blind 30
work_plane "WorkPlane3" AlongDistance -7.2 ExtraOffset 0
sketch "Keyed stem socket" plane through (-7.2, 0, 0) normal (1, 0, 0) x axis (0, 0, -1)
  line L1 (-164, 7.2) -> (-164, -7.2)
  line L2 (-196, 7.2) -> (-164, 7.2)
  line L3 (-196, -7.2) -> (-196, 7.2)
  line L4 (-164, -7.2) -> (-196, -7.2)
extrude "Extrude2" cut sketch "Keyed stem socket" along normal blind 14.4
work_plane "WorkPlane4" AlongDistance -0.1 ExtraOffset 0
sketch "Grip screw bore" plane through (-0.1, 0, 0) normal (1, 0, 0) x axis (0, 0, -1)
  circle C1 centre (-180, 0) radius 1.7
extrude "Extrude3" cut sketch "Grip screw bore" along normal blind 26
work_plane "WorkPlane5" AlongDistance 12.5 ExtraOffset 0
sketch "Recessed grip screw head" plane through (12.5, 0, 0) normal (1, 0, 0) x axis (0, 0, -1)
  circle C1 centre (-180, 0) radius 3.1
extrude "Extrude4" cut sketch "Recessed grip screw head" along normal blind 14
work_plane "WorkPlane6" AlongDistance -0.1 ExtraOffset 0
sketch "Grip screw bore (1)" plane through (-0.1, 0, 0) normal (1, 0, 0) x axis (0, 0, -1)
  circle C1 centre (-190, 0) radius 1.7
extrude "Extrude5" cut sketch "Grip screw bore (1)" along normal blind 26
work_plane "WorkPlane7" AlongDistance 12.5 ExtraOffset 0
sketch "Recessed grip screw head (1)" plane through (12.5, 0, 0) normal (1, 0, 0) x axis (0, 0, -1)
  circle C1 centre (-190, 0) radius 3.1
extrude "Extrude6" cut sketch "Recessed grip screw head (1)" along normal blind 14
work_plane "WorkPlane1" AlongDistance 4 ExtraOffset 0
sketch "First strong flat cheek" plane through (4, 0, 0) normal (1, 0, 0) x axis (0, 0, -1)
  line L1 (-6, -5) -> (-6, -61)
  line L2 (-7, 0) -> (-6, -5)
  line L3 (-17, 0) -> (-7, 0)
  line L4 (-18, -5) -> (-17, 0)
  line L5 (-18, -61) -> (-18, -5)
  line L6 (-6, -61) -> (-18, -61)
extrude "Extrude1" new body sketch "First strong flat cheek" along normal blind 3 bodies "P11 Forked roller follower"
work_plane "WorkPlane2" AlongDistance 4 ExtraOffset 0
sketch "Spring tail bridge" plane through (4, 0, 0) normal (1, 0, 0) x axis (0, 0, -1)
  line L1 (-6, -49) -> (-6, -61)
  line L2 (-18, -49) -> (-6, -49)
  line L3 (-18, -61) -> (-18, -49)
  line L4 (-6, -61) -> (-18, -61)
extrude "Extrude2" add sketch "Spring tail bridge" along normal blind 16
work_plane "WorkPlane3" AlongDistance 17 ExtraOffset 0
sketch "Second supporting cheek" plane through (17, 0, 0) normal (1, 0, 0) x axis (0, 0, -1)
  line L1 (-6, -5) -> (-6, -61)
  line L2 (-7, 0) -> (-6, -5)
  line L3 (-17, 0) -> (-7, 0)
  line L4 (-18, -5) -> (-17, 0)
  line L5 (-18, -61) -> (-18, -5)
  line L6 (-6, -61) -> (-18, -61)
extrude "Extrude3" add sketch "Second supporting cheek" along normal blind 3
work_plane "WorkPlane4" AlongDistance 4 ExtraOffset 0
sketch "Rounded roller cheek" plane through (4, 0, 0) normal (1, 0, 0) x axis (0, 0, -1)
  circle C1 centre (-12, 0) radius 6
extrude "Extrude4" add sketch "Rounded roller cheek" along normal blind 3
work_plane "WorkPlane5" AlongDistance 17 ExtraOffset 0
sketch "Rounded roller cheek (1)" plane through (17, 0, 0) normal (1, 0, 0) x axis (0, 0, -1)
  circle C1 centre (-12, 0) radius 6
extrude "Extrude5" add sketch "Rounded roller cheek (1)" along normal blind 3
work_plane "WorkPlane6" AlongDistance 3.9 ExtraOffset 0
sketch "Smooth pivot sleeve bore" plane through (3.9, 0, 0) normal (1, 0, 0) x axis (0, 0, -1)
  circle C1 centre (-12, -35) radius 4.15
extrude "Extrude6" cut sketch "Smooth pivot sleeve bore" along normal blind 16.2
work_plane "WorkPlane7" AlongDistance 3.9 ExtraOffset 0
sketch "Roller axle holes" plane through (3.9, 0, 0) normal (1, 0, 0) x axis (0, 0, -1)
  circle C1 centre (-12, 0) radius 1.7
extrude "Extrude7" cut sketch "Roller axle holes" along normal blind 16.2
work_plane "WorkPlane8" AlongDistance 3.9 ExtraOffset 0
sketch "Roller M3 nut recess" plane through (3.9, 0, 0) normal (1, 0, 0) x axis (0, 0, -1)
  line L1 (-14.9, 1.6743) -> (-12, 3.3486)
  line L2 (-14.9, -1.6743) -> (-14.9, 1.6743)
  line L3 (-12, -3.3486) -> (-14.9, -1.6743)
  line L4 (-9.1, -1.6743) -> (-12, -3.3486)
  line L5 (-9.1, 1.6743) -> (-9.1, -1.6743)
  line L6 (-12, 3.3486) -> (-9.1, 1.6743)
extrude "Extrude8" cut sketch "Roller M3 nut recess" along normal blind 1.6
work_plane "WorkPlane9" AlongDistance 18 ExtraOffset 0
sketch "Spring tail locating pilot" plane through (0, 0, 18) normal (0, 0, 1) x axis (1, 0, 0)
  circle C1 centre (12, -55) radius 1.8
extrude "Extrude9" add sketch "Spring tail locating pilot" along normal blind 2
work_plane "WorkPlane1" AlongDistance -24 ExtraOffset 0
sketch "Captured spring reaction block" plane through (-24, 0, 0) normal (1, 0, 0) x axis (0, 0, -1)
  line L1 (-38, -44) -> (-38, -66)
  line L2 (-52, -44) -> (-38, -44)
  line L3 (-52, -66) -> (-52, -44)
  line L4 (-38, -66) -> (-52, -66)
extrude "Extrude1" new body sketch "Captured spring reaction block" along normal blind 48
work_plane "WorkPlane2" AlongDistance -24.1 ExtraOffset 0
sketch "Left M3 insert with screw tip relief" plane through (-24.1, 0, 0) normal (1, 0, 0) x axis (0, 0, -1)
  circle C1 centre (-44, -59) radius 2
extrude "Extrude2" cut sketch "Left M3 insert with screw tip relief" along normal blind 8.8
work_plane "WorkPlane3" AlongDistance 15.3 ExtraOffset 0
sketch "Right M3 insert with screw tip relief" plane through (15.3, 0, 0) normal (1, 0, 0) x axis (0, 0, -1)
  circle C1 centre (-44, -59) radius 2
extrude "Extrude3" cut sketch "Right M3 insert with screw tip relief" along normal blind 8.8
work_plane "WorkPlane4" AlongDistance -24.1 ExtraOffset 0
sketch "Left M3 insert with screw tip relief (1)" plane through (-24.1, 0, 0) normal (1, 0, 0) x axis (0, 0, -1)
  circle C1 centre (-44, -51) radius 2
extrude "Extrude4" cut sketch "Left M3 insert with screw tip relief (1)" along normal blind 8.8
work_plane "WorkPlane5" AlongDistance 15.3 ExtraOffset 0
sketch "Right M3 insert with screw tip relief (1)" plane through (15.3, 0, 0) normal (1, 0, 0) x axis (0, 0, -1)
  circle C1 centre (-44, -51) radius 2
extrude "Extrude5" cut sketch "Right M3 insert with screw tip relief (1)" along normal blind 8.8
work_plane "WorkPlane6" AlongDistance 37.9 ExtraOffset 0
sketch "M4 preload adjuster" plane through (0, 0, 37.9) normal (0, 0, 1) x axis (1, 0, 0)
  circle C1 centre (12, -55) radius 2.2
extrude "Extrude6" cut sketch "M4 preload adjuster" along normal blind 14.2
work_plane "WorkPlane7" AlongDistance 37.9 ExtraOffset 0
